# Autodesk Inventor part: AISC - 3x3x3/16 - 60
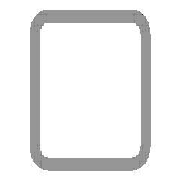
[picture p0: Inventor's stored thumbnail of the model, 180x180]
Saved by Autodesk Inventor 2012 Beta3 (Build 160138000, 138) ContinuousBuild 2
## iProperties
IsCustomPart: 1
Created: 2011-01
Part Number: AISC - 3x3x3/16 - 60
Material: Steel, Mild
Description: Tube
Document SubType Name: Modeling
Standard: ANSI
Designer: Beta-8540w
Standards Organization: ANSI
Language: en-US
Size Designation: 3x3x3/16
Categories: <MemberInstance><Categories><Category DisplayName="Structural Shapes" InternalName="089c4875-fa83-4c05-b084-43b9cc11f5ed" Mnemonic="GRDR"><CategoryParameter Dis
Stock Number: 3x3x3/16
Density: 7.86 g/cm^3
_CCFamilyMember: 9
_CCFamilyDisplayName: ANSI AISC (Square) - Tube
_FrameMemberDoc: Frame Member File
_Version: 15.0.0
_GetPNFromCC: 1
G_L: 60.000 in
G_W: 3.000 in
G_H: 3.000 in
Author: Beta-8540w
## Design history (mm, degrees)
node "Start plane"
node "End plane"
sketch "Sketch"
  geometry: L1 (-38.1, -28.575)-(-38.1, 28.575); L2 (-28.575, 38.1)-(28.575, 38.1); L3 (38.1, 28.575)-(38.1, -28.575); L4 (28.575, -38.1)-(-28.575, -38.1); L5 (-28.575, 33.337)-(28.575, 33.338); L6 (33.338, 28.575)-(33.338, -28.575); L7 (28.575, -33.337)-(-28.575, -33.338); L8 (-33.338, -28.575)-(-33.338, 28.575); L9 (0, 56.102)-(0, -56.102) reference; L10 (-56.102, 0)-(56.102, 0) reference; A1 r 9.525 centre (-28.575, -28.575) between (-38.1, -28.575) and (-28.575, -38.1); A2 r 9.525 centre (-28.575, 28.575) between (-28.575, 38.1) and (-38.1, 28.575); A3 r 9.525 centre (28.575, 28.575) between (38.1, 28.575) and (28.575, 38.1); A4 r 9.525 centre (28.575, -28.575) between (28.575, -38.1) and (38.1, -28.575); A5 r 4.763 centre (-28.575, 28.575) between (-28.575, 33.337) and (-33.338, 28.575); A6 r 4.763 centre (28.575, 28.575) between (33.338, 28.575) and (28.575, 33.338); A7 r 4.763 centre (28.575, -28.575) between (28.575, -33.337) and (33.338, -28.575); A8 r 4.763 centre (-28.575, -28.575) between (-33.338, -28.575) and (-28.575, -33.338)
  constraints: 16 end point, 16 point on circle, 8 centre point, 8 tangent, 4 parallel, 3 equal radius, 2 perpendicular, 7 other
  dimensions: "d10" = 76.2 distance between parallel lines of L2 L4 (= G_H); "d11" = 76.2 distance between parallel lines of L1 L3 (= G_W); "d12" = 4.7625 distance between parallel lines of L3 L6 (= G_T); "d15" = 38.1 distance between parallel lines of L2 L10 (= 0.5 x d10); "d16" = 38.1 distance between parallel lines of L9 L3 (= 0.5 x d11); "d17" = 9.525 radius of A1 (= G_IR)
extrude "Body" new body sketch "Sketch" stored distance "d3" = 1524 (= G_L); taper "d4" = 0 deg
node "Driven Length"
  sketch "Sketch3"
    geometry: L1 (0, 0)-(10, 0) reference
    constraints: 2 end point, 1 horizontal
  workplane "Work Plane3"
  sketch "Sketch4"
    geometry: L1 (-2, 0)-(12, 0) reference; L2 (-2, 1524)-(12, 1524) reference
    dimensions: "d19" = 1524 distance between parallel lines of L1 L2 (derived)
body "Solid1"
other parameters: "G_W" = 76.2 [user parameter; used in 1 equation term], "G_H" = 76.2 [user parameter; used in 1 equation term], "G_T" = 4.7625 [user parameter; used in 1 equation term], "G_IR" = 9.525 [user parameter; used in 1 equation term], "G_L" = 1524 (= d19) [user parameter; used in 1 equation term], "G_OFFSET_START" = 0 [user parameter; used in 1 equation term], "G_OFFSET_END" = 0 [user parameter; used in 1 equation term], "d13" = 0 (computed from G_OFFSET_START), "d14" = 1524 (= G_OFFSET_END + B_L), "B_L" = 1524 [user parameter; used in 1 equation term], "d18" = 90 deg
